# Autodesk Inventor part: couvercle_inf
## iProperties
Created: 2011-01
Part Number: couvercle_inf
Document SubType Name: Modeling
Designer: eric
Density: 1 g/cm^3
Mass: 42.085 g
Surface Area: 862.058 cm^2
Volume: 42.085 cm^3
Author: eric
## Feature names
1. Base1
